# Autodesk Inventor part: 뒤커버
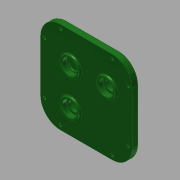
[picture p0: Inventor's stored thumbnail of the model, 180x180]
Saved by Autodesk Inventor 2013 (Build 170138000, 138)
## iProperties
Created: 2016-12
Part Number: 뒤커버
Material: 일반
Document SubType Name: Modeling
Designer: mduedu
Density: 1 g/cm^3
Mass: 179.104 g
Surface Area: 454.562 cm^2
Volume: 179.104 cm^3
Author: mduedu
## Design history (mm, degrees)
sketch "스케치1"
  geometry: L1 (-46, 42)-(-46, -36); L2 (-16, 72)-(62, 72); L3 (92, 42)-(92, -36); L4 (62, -66)-(-16, -66); A1 r 30 centre (-16, -36) between (-46, -36) and (-16, -66); A2 r 30 centre (62, 42) between (92, 42) and (62, 72); A3 r 30 centre (62, -36) between (62, -66) and (92, -36); A4 r 30 centre (-16, 42) between (-16, 72) and (-46, 42); 1 further point
  constraints: 8 end point, 8 point on circle, 8 tangent, 4 centre point, 3 equal radius, 2 perpendicular, 1 horizontal, 1 vertical
  dimensions: "d80" = 30 radius of A2; "d81" = 138 distance between parallel lines of L4 L2; "d82" = 92 distance from line of L3 point (0, 0); "d114" = 46 distance from line of L1 point (0, 0); "d115" = 72 distance from line of L2 point (0, 0)
extrude "돌출1" new body sketch "스케치1" distance "d3" = 10; taper "d4" = 0 deg
sketch "스케치2"
  geometry: C1 r 14 at (0, 26); 1 further point
  constraints: 1 centre point, 1 vertical alignment
  dimensions: "d5" = 28 diameter of C1; "d6" = 26 distance of C1.centre point (0, 0)
extrude "돌출2" join sketch "스케치2" distance "d7" = 3; taper "d8" = 0 deg
sketch "스케치3"
  geometry: C1 r 14 at (0, -28.87); C2 r 14 at (0, 26) reference; C3 r 14 at (54.87, 26); 1 further point
  constraints: 2 centre point, 1 horizontal alignment, 1 vertical alignment
  dimensions: "d9" = 28 diameter of C1; "d69" = 54.87 distance of C1.centre C2.centre; "d83" = 28 diameter of C3; "d84" = 54.87 distance of C3.centre C2.centre
extrude "돌출3" join sketch "스케치3" distance "d11" = 3; taper "d12" = 0 deg
hole "구멍1" diameter "d15" = 22; stored, may be unused: countersink angle "d19" = 90 deg, drill point angle "d21" = 0 deg; dims "d13" = 10, "d14" = 10, "d16" = 6, "d17" = 4, "d18" = 2, "d20" = 7
hole "구멍2" diameter "d24" = 18; stored, may be unused: countersink angle "d28" = 90 deg, drill point angle "d30" = 0 deg; dims "d22" = 10, "d23" = 10, "d25" = 6, "d26" = 4, "d27" = 2, "d29" = 1
hole "구멍3" diameter "d33" = 22; stored, may be unused: countersink angle "d37" = 90 deg, drill point angle "d39" = 0 deg; dims "d31" = 10, "d32" = 10, "d34" = 6, "d35" = 4, "d36" = 2, "d38" = 7
hole "구멍7" diameter "d87" = 22; stored, may be unused: countersink angle "d91" = 90 deg, drill point angle "d93" = 0 deg; dims "d85" = 10, "d86" = 10, "d88" = 6, "d89" = 4, "d90" = 2, "d92" = 7
sketch "스케치4"
  geometry: C1 r 14 at (0, -28.87) reference; C2 r 18 at (0, -28.87); C3 r 14 at (-54.87, 26) reference; C4 r 18 at (-54.87, 26); 1 further point
  constraints: 2 centre point, 2 coincident
  dimensions: "d40" = 36 diameter of C2; "d94" = 36 diameter of C4
extrude "돌출4" join sketch "스케치4" distance "d41" = 4; taper "d42" = 0 deg
hole "구멍4" diameter "d45" = 22; stored, may be unused: countersink angle "d49" = 90 deg, drill point angle "d51" = 0 deg; dims "d43" = 10, "d44" = 10, "d46" = 6, "d47" = 4, "d48" = 2, "d50" = 7
hole "구멍8" diameter "d97" = 22; stored, may be unused: countersink angle "d101" = 90 deg, drill point angle "d103" = 0 deg; dims "d95" = 10, "d96" = 10, "d98" = 6, "d99" = 4, "d100" = 2, "d102" = 7
hole "구멍5" diameter "d54" = 15; stored, may be unused: countersink angle "d58" = 90 deg, drill point angle "d60" = 0 deg; dims "d52" = 10, "d53" = 10, "d55" = 6, "d56" = 4, "d57" = 2, "d59" = 7
hole "구멍9" diameter "d106" = 15; stored, may be unused: countersink angle "d110" = 90 deg, drill point angle "d112" = 0 deg; dims "d104" = 10, "d105" = 10, "d107" = 6, "d108" = 4, "d109" = 2, "d111" = 7
fillet "모깎기1" dims "d61" = 0.3
fillet "모깎기2" dims "d62" = 2
chamfer "모따기1" distance "d63" = 1; stored, may be unused: second distance "d64" = 2, angle "d65" = 45 deg
fillet "모깎기3" dims "d66" = 2
fillet "모깎기4" dims "d67" = 2
fillet "모깎기5" dims "d68" = 2
sketch "스케치5"
  geometry: L1 (-62, 72)-(16, 72) reference; L2 (-92, -36)-(-92, 42) reference; L3 (16, -66)-(-62, -66) reference; L4 (46, 42)-(46, -36) reference; L5 (16, 66)-(-62, 66); L6 (-86, 42)-(-86, -36); L7 (-62, -60)-(16, -60); L8 (40, -36)-(40, 42); A1 r 30 centre (-62, 42) between (-62, 72) and (-92, 42) reference; A2 r 30 centre (-62, -36) between (-92, -36) and (-62, -66) reference; A3 r 30 centre (16, -36) between (16, -66) and (46, -36) reference; A4 r 30 centre (16, 42) between (46, 42) and (16, 72) reference; A5 r 24 centre (-62, 42) between (-62, 66) and (-86, 42); A6 r 24 centre (-62, -36) between (-86, -36) and (-62, -60); A7 r 24 centre (16, -36) between (16, -60) and (40, -36); A8 r 24 centre (16, 42) between (40, 42) and (16, 66)
  constraints: 8 end point, 8 point on circle, 4 centre point, 7 other
  dimensions: "d113" = 6 distance between parallel lines of L6 L2
sketch "스케치6"
  geometry: L1 (16, 66)-(-62, 66) reference; L2 (40, -36)-(40, 42) reference; L3 (-62, -60)-(16, -60) reference; L4 (-86, 42)-(-86, -36) reference; A1 r 24 centre (16, 42) between (40, 42) and (16, 66) reference; A2 r 24 centre (16, -36) between (16, -60) and (40, -36) reference; A3 r 24 centre (-62, -36) between (-86, -36) and (-62, -60) reference; A4 r 24 centre (-62, 42) between (-62, 66) and (-86, 42) reference; 8 further points
  constraints: 8 coincident
hole "구멍6" sketch "스케치6" at (-62, 66), (-86, 42), (-86, -36), (-62, -60), (16, -60), (40, -36), (40, 42), (16, 66) diameter "d71" = 4.5; stored, may be unused: countersink angle "d75" = 90 deg, drill point angle "d77" = 0 deg; dims "d72" = 6, "d73" = 8, "d74" = 4.6, "d76" = 8
node "솔리드1"
